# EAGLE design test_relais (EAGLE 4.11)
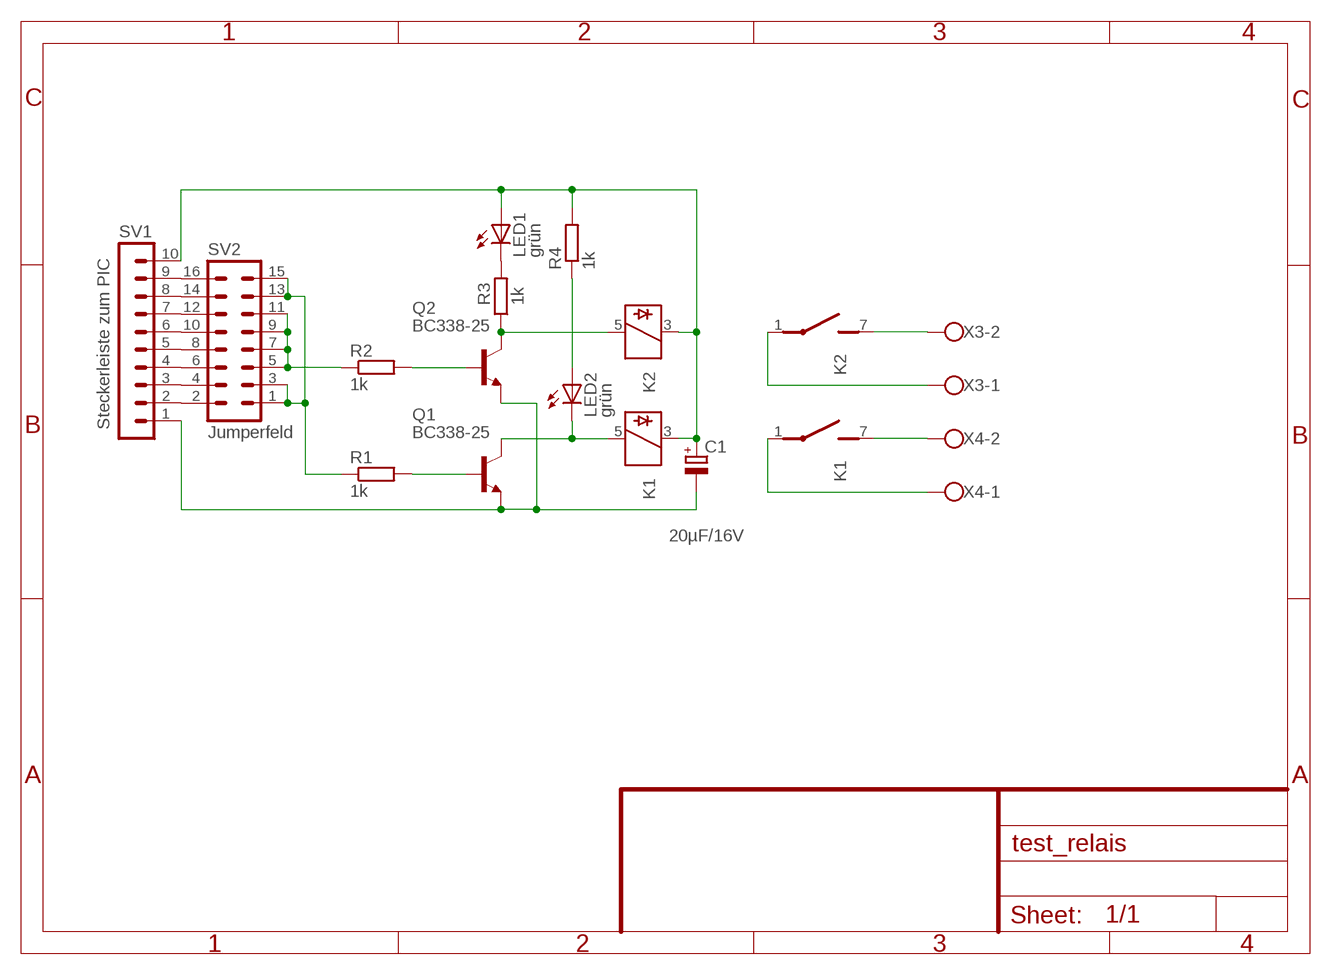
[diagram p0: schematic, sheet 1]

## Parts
C1  20µF/16V  CPOL-EUE2.5-5  [E2,5-5]
K1  35701331  [REED]
K2  35701331  [REED]
LED1  grün  LED3MM  [LED3MM]
LED2  grün  LED3MM  [LED3MM]
Q1  BC338-25  [TO92-EBC]
Q2  BC338-25  [TO92-EBC]
R1  1k  R-EU_0207/10  [0207/10]
R2  1k  R-EU_0207/10  [0207/10]
R3  1k  R-EU_0207/10  [0207/10]
R4  1k  R-EU_0207/10  [0207/10]
SV1  Steckerleiste zum PIC  MA10-1W  [MA10-1W]
SV2  Jumperfeld  MA08-2  [MA08-2]
X3  W237-102  [W237-102]
X4  W237-102  [W237-102]

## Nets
N$1: SV1.2 SV2.2
N$2: SV1.3 SV2.4
N$3: SV1.4 SV2.6
N$4: SV1.5 SV2.8
N$5: SV1.6 SV2.10
N$6: SV1.7 SV2.12
N$7: SV1.8 SV2.14
N$8: SV1.9 SV2.16
N$9: R1.1 SV2.1 SV2.3 SV2.13 SV2.15
N$10: R2.1 SV2.5 SV2.7 SV2.9 SV2.11
N$11: K2.5 Q2.C R3.1
N$12: K1.5 LED2.K(C) Q1.C
N$13: LED1.K(C) R3.2
N$14: LED2.A R4.1
N$15: Q2.B R2.2
N$16: Q1.B R1.2
N$17: C1.- Q1.E Q2.E SV1.1
N$18: K2.7(2:S) X3.2
N$19: K2.1(2:P) X3.1
N$23: C1.+ K1.3 K2.3 LED1.A R4.2 SV1.10
N$24: K1.7(2:S) X4.2
N$25: K1.1(2:P) X4.1

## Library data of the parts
C1 = rcl:CPOL-EU: POLARIZED CAPACITOR, European symbol
K1 K2 = relay:35701331: RELAY reed, 1 x norm. open with polarity
LED1 LED2 = led:LED: LED
Q1 Q2 = transistor-npn:BC338*: NPN Transistor
R1-R4 = rcl:R-EU_: RESISTOR, European symbol
SV1 = con-lstb:MA10-1W: PIN HEADER
SV2 = con-lstb:MA08-2: PIN HEADER
X3 X4 = con-wago-500:W237-102: WAGO SCREW CLAMP

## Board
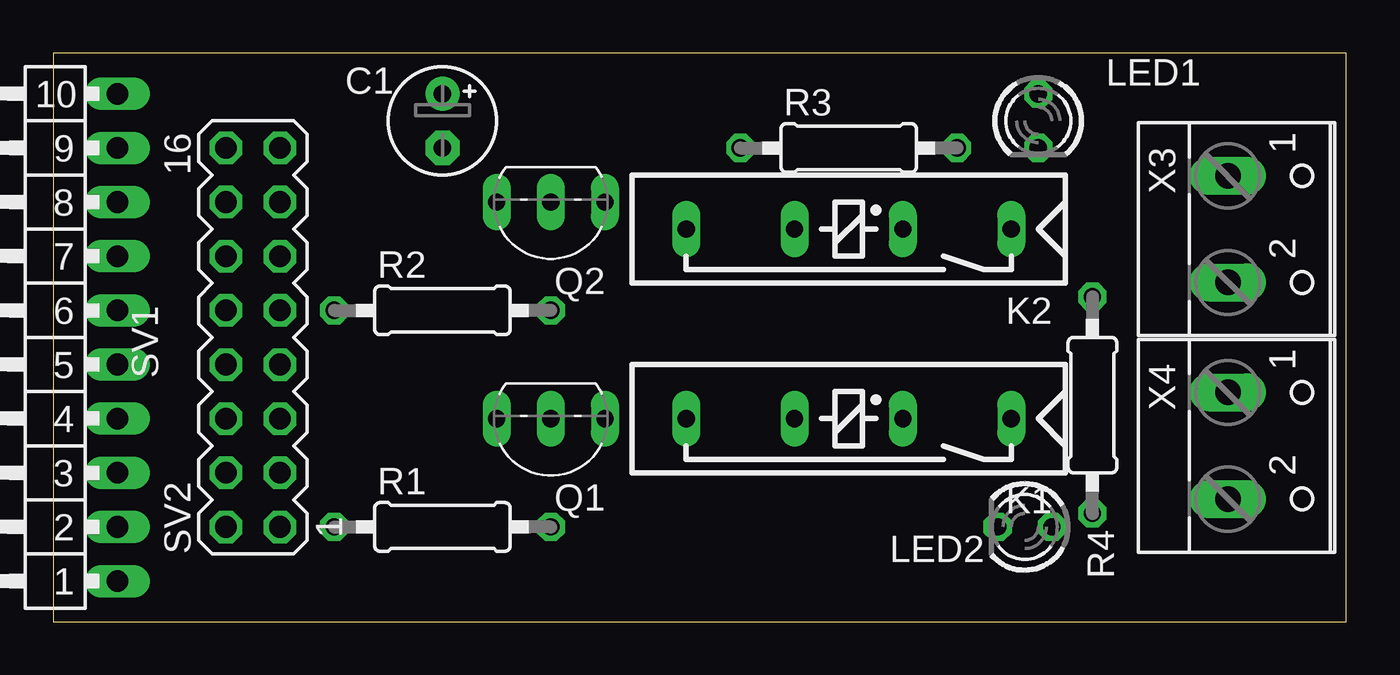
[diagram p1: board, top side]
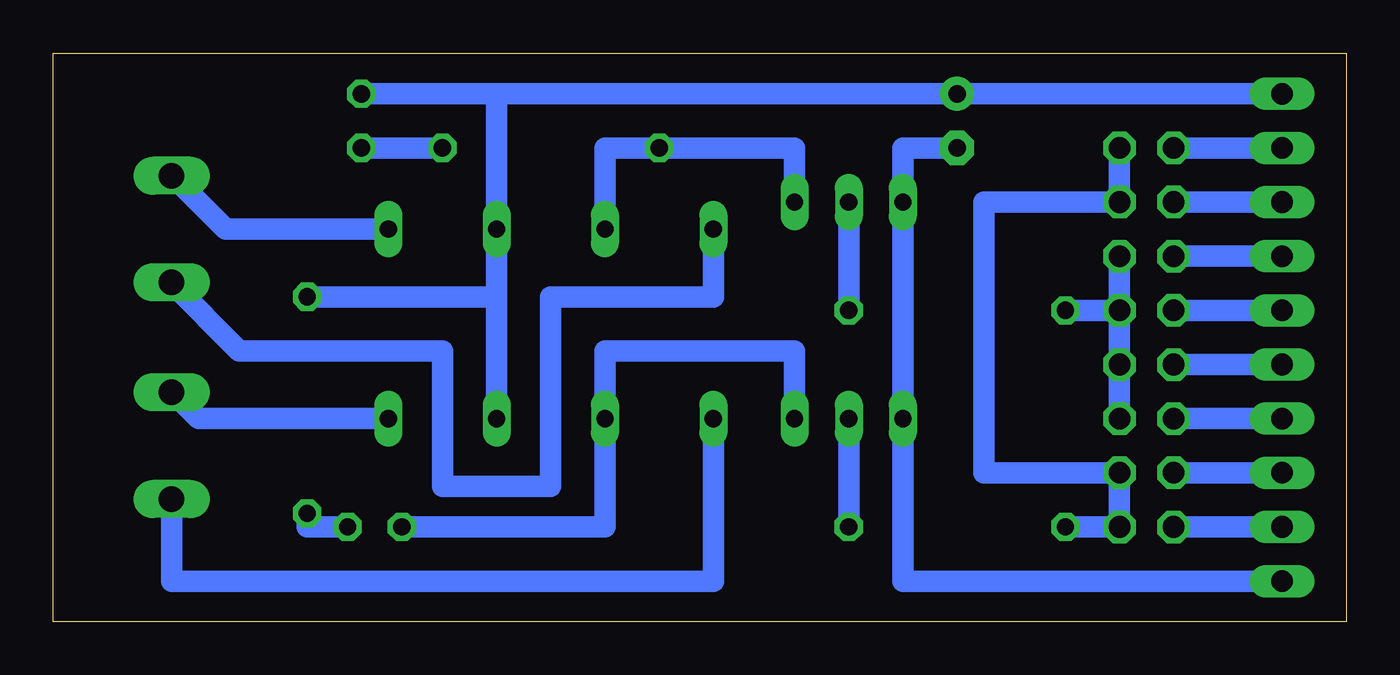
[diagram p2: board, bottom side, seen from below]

Size 60.63 x 26.66 mm. Coordinates in mm from the lower left corner, seen from the top.
Outline: 0,0 60.63,0 60.63,26.66 0,26.66 0,0
Copper layers (1*16): Top 0.035mm / dielectric 1.5mm / Bottom 0.035mm
Design rules "default": minimum track width 10mil, minimum drill 10mil, track to track 8mil, track to pad 8mil, pad to pad 8mil, via to via 8mil, smd to smd 8mil, copper to edge 40mil, drill to drill 8mil, minimum pad ring 10mil, minimum via ring 8mil, stop-mask expansion 4mil, vias tented up to drill 0mil, thermal gap 10mil

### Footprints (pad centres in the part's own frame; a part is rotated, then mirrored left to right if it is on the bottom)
E2,5-5 = drill 0.813 pad 1.6 round: + -1.27,0 | drill 0.813 pad 1.6 octagon: - 1.27,0
REED = drill 0.813 long: 1 -17.78,2.54; 3 -12.7,2.54; 5 -7.62,2.54; 7 -2.54,2.54
LED3MM = drill 0.813 octagon: A -1.27,0; K 1.27,0
TO92-EBC = drill 0.813 long: B 0,-1.27; C -2.54,-1.27; E 2.54,-1.27
0207/10 = drill 0.813 octagon: 1 -5.08,0; 2 5.08,0
MA10-1W = drill 1.016 long: 1 -11.43,0; 2 -8.89,0; 3 -6.35,0; 4 -3.81,0; 5 -1.27,0; 6 1.27,0; 7 3.81,0; 8 6.35,0; 9 8.89,0; 10 11.43,0
MA08-2 = drill 1.016 octagon: 1 -8.89,-1.27; 2 -8.89,1.27; 3 -6.35,-1.27; 4 -6.35,1.27; 5 -3.81,-1.27; 6 -3.81,1.27; 7 -1.27,-1.27; 8 -1.27,1.27; 9 1.27,-1.27; 10 1.27,1.27; 11 3.81,-1.27; 12 3.81,1.27; 13 6.35,-1.27; 14 6.35,1.27; 15 8.89,-1.27; 16 8.89,1.27
W237-102 = drill 1.194 long: 1 -2.5,-1.27; 2 2.5,-1.27

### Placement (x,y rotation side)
C1  18.25,23.49 270 top
K1  27.14,12.06 180 top
K2  27.14,20.95 180 top
LED1  46.19,23.49 270 top
LED2  45.55,4.44 180 top
Q1  23.33,8.25 180 top
Q2  23.33,18.41 180 top
R1  18.25,4.44 0 top
R2  18.25,14.6 0 top
R3  37.3,22.22 0 top
R4  48.73,10.16 90 top
SV1  3.01,13.33 90 top
SV2  9.36,13.33 90 top
X3  56.35,18.41 270 top
X4  56.35,8.25 270 top

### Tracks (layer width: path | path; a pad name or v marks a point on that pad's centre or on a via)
N$1
  Bottom 1.016: SV1.2 SV2.2
N$2
  Bottom 1.016: SV1.3 SV2.4
N$3
  Bottom 1.016: SV1.4 SV2.6
N$4
  Bottom 1.016: SV1.5 SV2.8
N$5
  Bottom 1.016: SV1.6 SV2.10
N$6
  Bottom 1.016: SV1.7 SV2.12
N$7
  Bottom 1.016: SV1.8 SV2.14
N$8
  Bottom 1.016: SV1.9 SV2.16
N$9
  Bottom 1.016: SV2.15 SV2.13 16.98,19.68 16.98,6.98 SV2.3 SV2.1 R1.1
N$10
  Bottom 1.016: SV2.9 SV2.11 | SV2.5 SV2.7 SV2.9 | SV2.9 R2.1
N$11
  Bottom 1.016: Q2.C 25.87,22.22 R3.1 34.76,22.22 K2.5
N$12
  Bottom 1.016: Q1.C 25.87,12.7 34.76,12.7 K1.5 34.76,4.44 LED2.K
N$13
  Bottom 1.016: R3.2 LED1.K
N$14
  Bottom 1.016: R4.1 48.73,4.44 LED2.A
N$15
  Bottom 1.016: R2.2 Q2.B
N$16
  Bottom 1.016: R1.2 Q1.B
N$17
  Bottom 1.016: SV1.1 20.79,1.9 Q1.E Q2.E 20.79,22.22 C1.-
N$18
  Bottom 0.406: 55.08,15.87 X3.2
  Bottom 1.016: K2.7 29.68,15.23 37.3,15.23 37.3,6.34 42.38,6.34 42.38,12.7 51.91,12.7 55.08,15.87
N$19
  Bottom 0.406: 55.08,20.95 X3.1
  Bottom 1.016: K2.1 52.54,18.41 55.08,20.95
N$23
  Bottom 1.016: 39.84,15.23 K2.3 39.84,24.76 | 39.84,15.23 K1.3 | C1.+ SV1.10 39.84,24.76 | 39.84,24.76 LED1.A | 39.84,15.23 R4.2
N$24
  Bottom 1.016: K1.7 29.68,1.9 55.08,1.9 X4.2
N$25
  Bottom 0.406: 55.08,10.79 X4.1
  Bottom 1.016: K1.1 53.81,9.52 55.08,10.79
